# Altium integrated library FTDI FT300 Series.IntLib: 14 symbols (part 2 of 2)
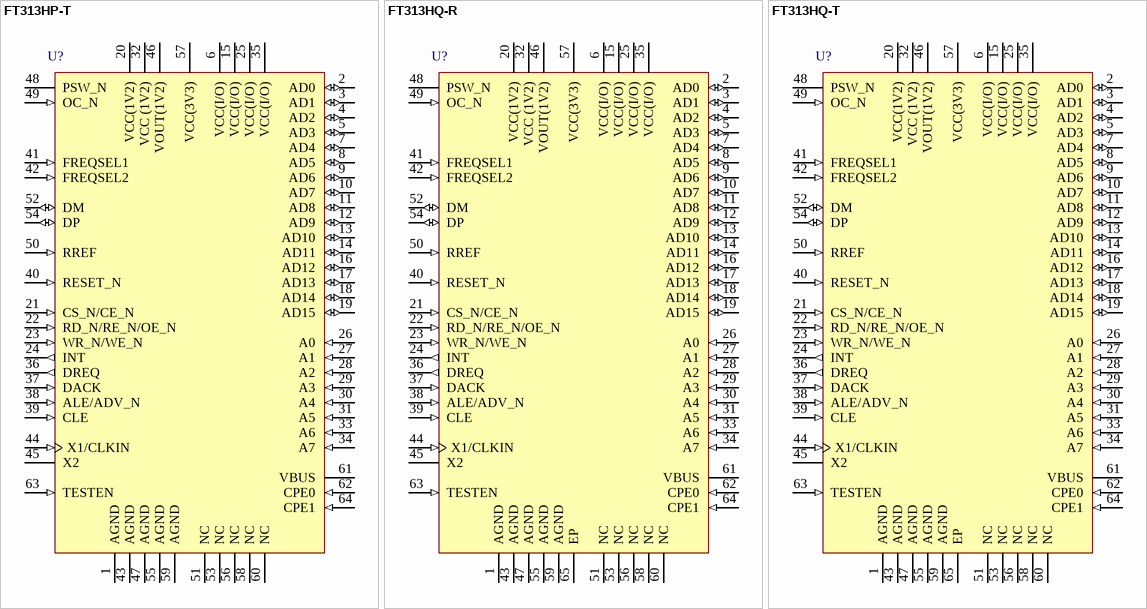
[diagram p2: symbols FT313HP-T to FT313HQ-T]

## FT313HQ-T
designator U?
FT313H Single Chip USB2.0 HS Embedded Host Controller, -40 to +85 degC, 64-pin QFN, Pb-Free, Tray; Manufacturer: FTDI; PartNumber: FT313HQ-T
footprint QFN-64_N (QFN, 64-Leads, Body 9.1x9.1mm, Pitch 0.5mm, Thermal Pad 3.78x3.78mm, IPC Medium Density)
footprint QFN-64_N (QFN, 64-Leads, Body 9.1x9.1mm, Pitch 0.5mm, Thermal Pad 3.78x3.78mm, IPC High Density)
footprint QFN-64_M (QFN, 64-Leads, Body 9.1x9.1mm, Pitch 0.5mm, Thermal Pad 3.78x3.78mm, IPC Low Density)
pins: 1 AGND (power) "Analog Ground", 2 AD0 (io) "Bit 0 of the address and data bus. Bidirectional pad; push-pull, three-state output. 3.3V tolerant", 3 AD1 (io) "Bit 1 of the address and data bus. Bidirectional pad; push-pull, three-state output. 3.3V tolerant", 4 AD2 (io) "Bit 2 of the address and data bus. Bidirectional pad; push-pull, three-state output. 3.3V tolerant", 5 AD3 (io) "Bit 3 of the address and data bus. Bidirectional pad; push-pull, three-state output. 3.3V tolerant", 6 VCC(I/O) (power) "I/O supply voltage; connect a 0.1uF decoupling capacitor. 1.8V, 2.5V or 3.3V", 7 AD4 (io) "Bit 4 of the address and data bus. Bidirectional pad; push-pull, three-state output. 3.3V tolerant", 8 AD5 (io) "Bit 5 of the address and data bus. Bidirectional pad; push-pull, three-state output. 3.3V tolerant", 9 AD6 (io) "Bit 6 of the address and data bus. Bidirectional pad; push-pull, three-state output. 3.3V tolerant", 10 AD7 (io) "Bit 7 of the address and data bus. Bidirectional pad; push-pull, three-state output. 3.3V tolerant", 11 AD8 (io) "Bit 8 of the address and data bus. Bidirectional pad; push-pull, three-state output. 3.3V tolerant", 12 AD9 (io) "Bit 9 of the address and data bus. Bidirectional pad; push-pull, three-state output. 3.3V tolerant", 13 AD10 (io) "Bit 10 of the address and data bus. Bidirectional pad; push-pull, three-state output. 3.3V tolerant", 14 AD11 (io) "Bit 11 of the address and data bus. Bidirectional pad; push-pull, three-state output. 3.3V tolerant", 15 VCC(I/O) (power) "I/O supply voltage; connect a 0.1uF decoupling capacitor. 1.8V, 2.5V or 3.3V", 16 AD12 (io) "Bit 12 of the address and data bus. Bidirectional pad; push-pull, three-state output. 3.3V tolerant", 17 AD13 (io) "Bit 13 of the address and data bus. Bidirectional pad; push-pull, three-state output. 3.3V tolerant", 18 AD14 (io) "Bit 14 of the address and data bus. Bidirectional pad; push-pull, three-state output. 3.3V tolerant", 19 AD15 (io) "Bit 15 of the address and data bus. Bidirectional pad; push-pull, three-state output. 3.3V tolerant", 20 VCC(1V2) (power) "Core power 1.2V input; for normal operation, this pin must be connected to pin 46. Connect a 0.1uF decoupling capacitor", 21 CS_N/CE_N (in), 22 RD_N/RE_N/OE_N (in), 23 WR_N/WE_N (in), 24 INT (out) "Interrupt output. Push-pull output; 3.3V tolerant", 25 VCC(I/O) (power) "I/O supply voltage; connect a 0.1uF decoupling capacitor. 1.8V, 2.5V or 3.3V", 26 A0 (in) "Bit 0 of the address bus; when not in use, connect to GND. Input; 3.3V tolerant", 27 A1 (in) "Bit 1 of the address bus; when not in use, connect to GND. Input; 3.3V tolerant", 28 A2 (in) "Bit 2 of the address bus; when not in use, connect to GND. Input; 3.3V tolerant", 29 A3 (in) "Bit 3 of the address bus; when not in use, connect to GND. Input; 3.3V tolerant", 30 A4 (in) "Bit 4 of the address bus; when not in use, connect to GND. Input; 3.3V tolerant", 31 A5 (in) "Bit 5 of the address bus; when not in use, connect to GND. Input; 3.3V tolerant", 32 VCC (1V2) (power) "Core power 1.2V input; for normal operation, this pin must be connected to pin 46. Connect a 0.1uF decoupling capacitor.", 33 A6 (in) "Bit 6 of the address bus; when not in use, connect to GND. Input; 3.3V tolerant", 34 A7 (in) "Bit 7 of the address bus; when not in use, connect to GND. Input; 3.3V tolerant", 35 VCC(I/O) (power) "I/O supply voltage; connect a 0.1uF decoupling capacitor. 1.8V, 2.5V or 3.3V", 36 DREQ (out) "DMA request; Push-pull output; 3.3V tolerant", 37 DACK (in) "DMA acknowledge; Internal pull-down. Input; 3.3V tolerant", 38 ALE/ADV_N (in), 39 CLE (in) "Command latch enable. Input; 3.3V tolerant", 40 RESET_N (in) "Chip reset; Internal pull-up. Input; 3.3V tolerant", 41 FREQSEL1 (in) "Input clock frequency selection pin1. Input; 3.3V tolerant", 42 FREQSEL2 (in) "Input clock frequency selection pin2. Input; 3.3V tolerant", 43 AGND (power) "Analog Ground", 44 X1/CLKIN (in) "Crystal oscillator or clock input; 3.3V peak input allowed", 45 X2 "Crystal oscillator output; leave open if an external clock is applied on pin X1/CLKIN", 46 VOUT(1V2) (power) "Internal 1.2V regulator output; connect 4.7uF and 0.1uF decoupling capacitors to this pin.", 47 AGND (power) "Analog Ground", 48 PSW_N (oc) "Port power switch; when not in use, connect to VCC(3V3) through a 10kOhm resistor. Open drain output; 5V tolerant", 49 OC_N (in) "Over current input; when not in use, connect to VCC(3V3) through a 10KOhm resistor. Input; 5V tolerant", 50 RREF (in) "Port reference resistor connection. Connect 12 kOhm±1% resistor between RREF and GND", 51 NC "No connect", 52 DM (io) "Port DM; connect to the D- pin of the USB connector", 53 NC "No connect", 54 DP (io) "Port DP; connect to the D+ pin of the USB connector", 55 AGND (power) "Analog Ground", 56 NC "No connect", 57 VCC(3V3) (power) "Supply 3.3V voltage; Connect 10uF and 0.1uF decoupling capacitors", 58 NC "No connect", 59 AGND (power) "Analog Ground", 60 NC "No connect", 61 VBUS (power) "VBUS discharge. 5V tolerant", 62 CPE0 (in) "Bit 0 to select charging port emulation type", 63 TESTEN (in) "Enable test mode. Internal pull-down. For normal operation leave floating.", 64 CPE1 (in) "Bit 1 to select charging port emulation type", 65 EP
